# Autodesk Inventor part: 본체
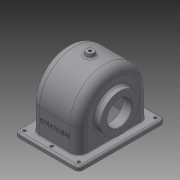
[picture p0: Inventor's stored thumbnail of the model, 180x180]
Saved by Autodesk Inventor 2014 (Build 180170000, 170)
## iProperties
Created: 2015-09
Part Number: 본체
Material: 일반
Document SubType Name: Modeling
Designer: USER
Density: 1 g/cm^3
Appearance: 기본값
Author: USER
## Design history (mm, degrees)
sketch "스케치2"
  geometry: L1 (-57, 0)-(-57, -40); L2 (57, 0)-(57, -40); L3 (57, -40)-(-57, -40); A1 r 57 centre (0, 0) between (57, 0) and (-57, 0); 1 further point
  constraints: 6 end point, 2 point on circle, 2 tangent, 1 centre point, 1 coincident, 1 parallel, 1 vertical
  dimensions: "d3" = 114 diameter of A1; "d4" = 40 distance of L1.start L1.end; "d5" = 40 distance of L2.start L2.end
extrude "돌출1" new body sketch "스케치2" distance "d6" = 77; taper "d7" = 0 deg
node "작업 평면1"
sketch "스케치3"
  geometry: L1 (0, 57)-(77, 57) reference; L2 (0, -57)-(77, -57) reference; L3 (14, 0)-(63, 0); L4 (38.5, 57)-(38.5, -57); L5 (-13.5, 0)-(90.5, 0); L6 (-13.5, 70)-(-13.5, -70); L7 (-13.5, 70)-(90.5, 70); L8 (90.5, 70)-(90.5, -70); L9 (90.5, -70)-(-13.5, -70); L10 (0, -57)-(0, 57) reference; L11 (77, 57)-(77, -57) reference; 2 further points
  constraints: 14 end point, 5 midpoint, 4 perpendicular
  dimensions: "d11" = 104 distance of L5.start L5.end; "d12" = 140 distance of L6.start L6.end; "d13" = 104 distance of L6.start L7.end; "d14" = 140 distance of L7.end L8.end
extrude "돌출2" join sketch "스케치3" distance "d15" = 7; taper "d16" = 0 deg
fillet "모깎기2" dims "d17" = 7
fillet "모깎기3" dims "d18" = 3
sketch "스케치4"
  geometry: L1 (-13.5, 63)-(-13.5, -63) reference; L2 (83.5, 70)-(-6.5, 70) reference; L3 (90.5, -63)-(90.5, 63) reference; L4 (-6.5, -70)-(83.5, -70) reference; C1 r 2.5 at (38.5, 62); C2 r 2.5 at (-5.5, 62); C3 r 2.5 at (82.5, 62); C4 r 2.5 at (-5.5, -62); C5 r 2.5 at (38.5, -62); C6 r 2.5 at (82.5, -62); 1 further point
  constraints: 6 centre point, 2 horizontal alignment
  dimensions: "d24" = 5 diameter of C1; "d27" = 5 diameter of C2; "d28" = 5 diameter of C3; "d29" = 5 diameter of C4; "d30" = 5 diameter of C5; "d31" = 5 diameter of C6; "d32" = 8 distance from line of C2.centre L1; "d33" = 8 distance from line of L2 C2.centre; "d34" = 8 distance from line of L2 C3.centre; "d35" = 8 distance from line of C3.centre L3; "d36" = 44 distance of C1.centre C2.centre; "d37" = 44 distance of C3.centre C1.centre (derived); "d38" = 8 distance from line of C4.centre L1; "d39" = 8 distance from line of L4 C4.centre; "d40" = 44 distance of C5.centre C4.centre; "d41" = 8 distance from line of L4 C6.centre; "d42" = 8 distance from line of L3 C6.centre
extrude "돌출3" cut sketch "스케치4" distance "d43" = 7; taper "d44" = 0 deg
node "작업 평면3"
sketch "스케치12"
  geometry: C1 r 31 at (0, 0); A1 r 57 centre (0, 0) between (0, 57) and (0, -57) reference
  constraints: 1 centre point, 1 coincident
  dimensions: "d73" = 62 diameter of C1
extrude "돌출8" join sketch "스케치12" distance "d74" = 10; taper "d75" = 0 deg
node "작업 평면5"
sketch "스케치13"
  geometry: L1 (-57, -40)-(-57, 0) reference; L2 (-63, -47)-(63, -47) reference; L3 (57, 0)-(57, -40) reference; L4 (-51, -47)-(51, -47); L5 (-51, 0)-(-51, -47); L6 (51, 0)-(51, -47); A1 r 57 centre (0, 0) between (57, 0) and (-57, 0) reference; A2 r 51 centre (0, 0) between (51, 0) and (-51, 0); 1 further point
  constraints: 6 end point, 2 perpendicular, 2 point on circle, 2 point on line, 2 tangent, 1 centre point, 1 collinear
  dimensions: "d129" = 6 radial gap between concentric circles of A2 A1; "d130" = 102 distance between parallel lines of L6 L5 (derived)
extrude "돌출9" cut sketch "스케치13" stored distance "d80" = 67; taper "d81" = 0 deg
sketch "스케치14"
  geometry: L1 (0, 0)-(0, 57) reference; L2 (0, 0)-(0, -40) reference; L3 (-87, 31)-(-87, -31) reference; L4 (0, 0)-(-87, 0); L5 (-19, 0)-(-19, 28); L6 (-19, 28)-(0, 43.943); L7 (0, 0)-(0, 43.943); 1 further point
  constraints: 8 end point, 2 point on line, 1 collinear, 1 midpoint, 1 perpendicular
  dimensions: "d82" = 56 diameter of L5.end L4; "d83" = 50 deg angle of L5 L6; "d84" = 19 distance between parallel lines of L5 L1
revolve "회전2" sketch "스케치14" stored, may be unused: angle "d85" = 90 deg
sketch "스케치16"
  geometry: C1 r 33 at (0, 0); A1 r 57 centre (0, 0) between (0, -57) and (0, 57) reference
  constraints: 1 centre point, 1 coincident
  dimensions: "d95" = 66 diameter of C1
extrude "돌출10" cut sketch "스케치16" distance "d96" = 3; taper "d97" = 0 deg
sketch "스케치17"
  geometry: C1 r 31 at (0, 0) reference; C2 r 20 at (0, 0)
  constraints: 1 centre point, 1 coincident
  dimensions: "d98" = 40 diameter of C2
extrude "돌출11" cut sketch "스케치17" stored distance "d99" = 3; taper "d100" = 0 deg
sketch "스케치18"
  geometry: L1 (0, 33)-(0, -33) reference; L2 (-87, -20)-(-87, 20) reference; L3 (0, 0)-(0, 57) reference; L4 (-19, 28)-(-5, 39.747) reference; L5 (-5.263, 33)-(0, 37.416); L6 (0, 0)-(-87, 0); L7 (0, 33)-(-3, 33) reference; L8 (-3, 33)-(-3, -33) reference; L9 (-5.263, 33)-(-3, 33); L10 (-3, 33)-(-3, 0); L11 (0, 37.416)-(0, 0)
  constraints: 10 end point, 2 midpoint, 1 collinear, 1 parallel, 1 perpendicular, 1 point on line
  dimensions: "d101" = 5 distance between parallel lines of L4 L5
revolve "회전3" sketch "스케치18" stored, may be unused: angle "d102" = 90 deg
sketch "스케치19" dims "d103" = 48
  geometry: C1 r 20 at (0, 0) reference; C2 r 31 at (0, 0) reference; 2 further points
  constraints: 2 horizontal alignment, 1 coincident, 2 other
hole "구멍1" sketch "스케치19" at (-24, 0) diameter "d104" = 2.459; stored, may be unused: countersink angle "d108" = 90 deg, drill point angle "d110" = 118 deg; dims "d105" = 6, "d106" = 4, "d107" = 2, "d109" = 8
sketch "스케치20" dims "d114" = 56
  geometry: C1 r 20 at (0, 0) reference; C2 r 33 at (0, 0) reference; 2 further points
  constraints: 2 horizontal alignment, 1 coincident, 2 other
hole "구멍2" sketch "스케치20" at (28, 0) diameter "d115" = 2.459; stored, may be unused: countersink angle "d119" = 90 deg, drill point angle "d121" = 118 deg; dims "d116" = 7, "d117" = 4, "d118" = 2, "d120" = 9
sketch "스케치21"
  geometry: L1 (0, -40)-(0, 0) reference; L2 (0, -37.416)-(0, 37.416) reference; L3 (-6.5, -47)-(-13.5, -47) reference; 2 further points
  constraints: 1 other
  dimensions: "d125" = 30 vertical distance of point (38.5, -17) L3.end; "d126" = 38.5 distance from line of L1 point (38.5, -17)
feature "엠보싱1" sketch "스케치21" dims "d3" = 114, "d4" = 40, "d5" = 40, "d127" = 0.5, "d128" = 0
fillet "모깎기6" dims "d131" = 14
fillet "모깎기7" dims "d132" = 9
fillet "모깎기8" dims "d133" = 0.5
node "작업 평면6"
sketch "스케치22"
  geometry: L1 (83.5, 70)-(-6.5, 70) reference; L2 (-13.5, 63)-(-13.5, -63) reference; C1 r 6 at (38.5, 0); 3 further points
  constraints: 2 midpoint, 1 centre point, 1 horizontal alignment, 1 vertical alignment
  dimensions: "d135" = 12 diameter of C1
extrude "돌출12" join sketch "스케치22" stored distance "d136" = 3; taper "d137" = 10 deg
sketch "스케치23"
  geometry: C1 r 6 at (0, 0) reference; 2 further points
  constraints: 1 coincident
hole "구멍3" sketch "스케치23" at (0, 0) diameter "d138" = 4.459; stored, may be unused: countersink angle "d142" = 90 deg, drill point angle "d144" = 118 deg; dims "d139" = 7, "d140" = 4, "d141" = 2, "d143" = 9
fillet "모깎기9" dims "d145" = 3
fillet "모깎기10" dims "d146" = 1
fillet "모깎기11" dims "d147" = 3
chamfer "모따기1" distance "d148" = 1; stored, may be unused: second distance "d149" = 2, angle "d150" = 45 deg
node "솔리드1"
pattern_circular "원형 패턴1" dims angle "d112" = 360 deg
pattern_circular "원형 패턴2" dims angle "d123" = 360 deg
node "투영된 루프1"
other parameters: "d134" = 63
